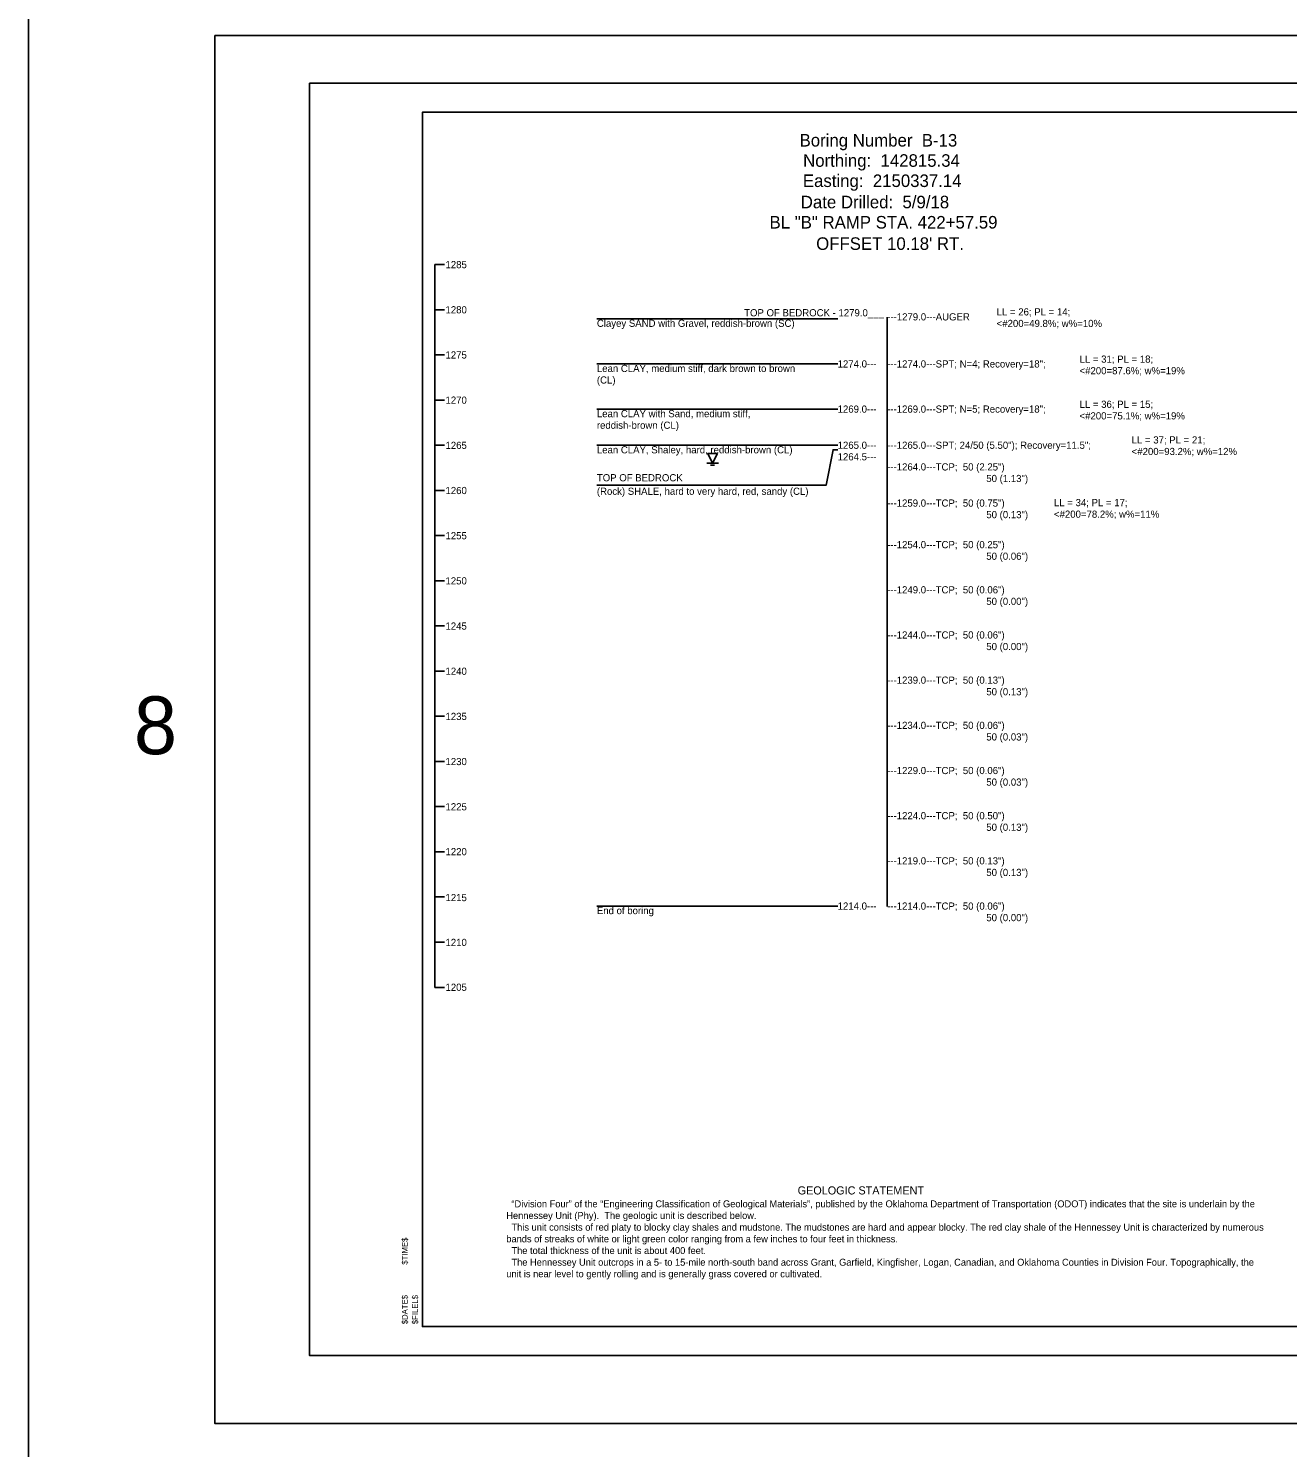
# Model space of a CAD drawing. Extents: x 2150162 to 2150245, y 143729 to 143865.
# Drawn here: x 2150203.4 to 2150225.17, y 143786.22 to 143810.76 of the extents above; entities that cross this region are included whole.
import ezdxf

# ---------------------------------------------------------------- set-up
doc = ezdxf.new("R2010")
doc.units = 0
for name, color, linetype in [('Default', 7, 'Continuous'), ('S', 7, 'Continuous'), ('SHT_Plot_Shape_Full', 7, 'Continuous'), ('SHT_Plot_Shape_Half', 7, 'Continuous'), ('SHT_Plot_Stamp', 7, 'Continuous'), ('SHT_Sheet_Border', 7, 'Continuous'), ('Text', 7, 'Continuous')]:
    doc.layers.add(name, color=color, linetype=linetype)

# ---------------------------------------------------------------- blocks, each defined once
blk = doc.blocks.new('Stamp_Plot_Stamp')
at = {"layer": 'SHT_Plot_Stamp'}
for s, p in [('$TIME$', (1.695, 1.572)), ('$DATE$', (1.695, 0.542)), ('$FILEL$', (1.873, 0.542))]:
    blk.add_text(s, height=0.1, rotation=90, dxfattribs=at).set_placement(p)
blk = doc.blocks.new('DGRFC_WTLEV1')
at = {"layer": 'Default'}
for points in [[(-0.0127, 0), (0.0127, 0)], [(0, 0), (0.0106, 0.0212), (-0.0106, 0.0212), (0, 0)], [(-0.0042, -0.0042), (0.0042, -0.0042)]]:
    blk.add_lwpolyline(points, dxfattribs=at)

msp = doc.modelspace()

# ---------------------------------------------------------------- linework, layer by layer
at = {"layer": 'Default'}
msp.add_line((2150210.432, 143794.179), (2150210.432, 143806.679), dxfattribs=at)
for points in [[(2150210.432, 143806.679), (2150210.599, 143806.679)], [(2150210.432, 143805.898), (2150210.599, 143805.898)], [(2150213.231, 143805.742), (2150217.398, 143805.742)], [(2150218.251, 143805.769), (2150218.251, 143795.579)], [(2150210.432, 143805.117), (2150210.599, 143805.117)], [(2150213.231, 143804.96), (2150217.398, 143804.96)], [(2150210.432, 143804.335), (2150210.599, 143804.335)], [(2150210.432, 143804.335), (2150210.599, 143804.335)], [(2150213.231, 143804.179), (2150217.398, 143804.179)], [(2150210.432, 143803.554), (2150210.599, 143803.554)], [(2150213.231, 143803.554), (2150217.398, 143803.554)], [(2150213.231, 143802.866), (2150217.196, 143802.866), (2150217.315, 143803.476), (2150217.398, 143803.476)], [(2150210.432, 143802.773), (2150210.599, 143802.773)], [(2150210.432, 143801.992), (2150210.599, 143801.992)], [(2150210.432, 143801.21), (2150210.599, 143801.21)], [(2150210.432, 143800.429), (2150210.599, 143800.429)], [(2150210.432, 143799.648), (2150210.599, 143799.648)], [(2150210.432, 143798.867), (2150210.599, 143798.867)], [(2150210.432, 143798.085), (2150210.599, 143798.085)], [(2150210.432, 143797.304), (2150210.599, 143797.304)], [(2150210.432, 143796.523), (2150210.599, 143796.523)], [(2150210.432, 143795.742), (2150210.599, 143795.742)], [(2150213.231, 143795.585), (2150217.398, 143795.585)], [(2150210.432, 143794.96), (2150210.599, 143794.96)], [(2150210.432, 143794.179), (2150210.599, 143794.179)]]:
    msp.add_lwpolyline(points, dxfattribs=at)
at = {"layer": 'S'}
msp.add_lwpolyline([(2150203.404, 143865.061), (2150245.24, 143865.061), (2150245.24, 143729.315), (2150203.404, 143729.315)], close=True, dxfattribs=at)
at = {"layer": 'SHT_Plot_Shape_Full'}
msp.add_lwpolyline([(2150206.628, 143810.637), (2150242.628, 143810.637), (2150242.628, 143786.637), (2150206.628, 143786.637)], close=True, dxfattribs=at)
at = {"layer": 'SHT_Plot_Shape_Half'}
msp.add_lwpolyline([(2150208.265, 143809.812), (2150242.265, 143809.812), (2150242.265, 143787.812), (2150208.265, 143787.812)], close=True, dxfattribs=at)
at = {"layer": 'SHT_Sheet_Border'}
msp.add_lwpolyline([(2150241.715, 143788.312), (2150210.215, 143788.312), (2150210.215, 143809.312), (2150241.715, 143809.312)], close=True, dxfattribs=at)

# ---------------------------------------------------------------- block references
at = {"layer": 'Default', "xscale": 7.873999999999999, "yscale": 7.873999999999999}
msp.add_blockref('DGRFC_WTLEV1', (2150215.231, 143803.242), dxfattribs=at)
at = {"layer": 'SHT_Plot_Stamp'}
msp.add_blockref('Stamp_Plot_Stamp', (2150208.265, 143787.812), dxfattribs=at)

# ---------------------------------------------------------------- texts
at = {"layer": 'Default'}
for s, height, p in [('Boring Number  B-13', 0.217, (2150216.735, 143808.719)), ('Northing:  142815.34', 0.217, (2150216.796, 143808.369)), ('Easting:  2150337.14', 0.217, (2150216.792, 143808.019)), ('Date Drilled:  5/9/18', 0.217, (2150216.756, 143807.651)), ('BL "B" RAMP STA. 422+57.59', 0.217, (2150216.216, 143807.301)), ("OFFSET 10.18' RT.", 0.217, (2150217.022, 143806.932)), ('1285', 0.124, (2150210.614, 143806.615)), ('1280', 0.124, (2150210.614, 143805.834)), ('TOP OF BEDROCK - 1279.0___', 0.124, (2150215.777, 143805.783)), ('---1279.0---AUGER', 0.124, (2150218.25, 143805.712)), ('LL = 26; PL = 14;', 0.124, (2150220.142, 143805.798)), ('Clayey SAND with Gravel, reddish-brown (SC)', 0.124, (2150213.231, 143805.601)), ('<#200=49.8%; w%=10%', 0.124, (2150220.142, 143805.598)), ('1275', 0.124, (2150210.614, 143805.053)), ('LL = 31; PL = 18;', 0.124, (2150221.575, 143804.981)), ('Lean CLAY, medium stiff, dark brown to brown', 0.124, (2150213.231, 143804.82)), ('1274.0---', 0.124, (2150217.393, 143804.898)), ('---1274.0---SPT; N=4; Recovery=18";', 0.124, (2150218.249, 143804.898)), ('<#200=87.6%; w%=19%', 0.124, (2150221.575, 143804.781)), ('(CL)', 0.124, (2150213.231, 143804.62)), ('1270', 0.124, (2150210.614, 143804.272)), ('Lean CLAY with Sand, medium stiff,', 0.124, (2150213.231, 143804.038)), ('1269.0---', 0.124, (2150217.393, 143804.117)), ('---1269.0---SPT; N=5; Recovery=18";', 0.124, (2150218.249, 143804.117)), ('<#200=75.1%; w%=19%', 0.124, (2150221.575, 143804)), ('LL = 36; PL = 15;', 0.124, (2150221.575, 143804.2)), ('reddish-brown (CL)', 0.124, (2150213.231, 143803.838)), ('1265', 0.124, (2150210.614, 143803.49)), ('1265.0---', 0.124, (2150217.393, 143803.492)), ('---1265.0---SPT; 24/50 (5.50"); Recovery=11.5";', 0.124, (2150218.249, 143803.492)), ('LL = 37; PL = 21;', 0.124, (2150222.476, 143803.584)), ('Lean CLAY, Shaley, hard, reddish-brown (CL)', 0.124, (2150213.231, 143803.413)), ('1264.5---', 0.124, (2150217.393, 143803.292)), ('<#200=93.2%; w%=12%', 0.124, (2150222.476, 143803.384)), ('---1264.0---TCP;  50 (2.25")', 0.124, (2150218.249, 143803.117)), ('TOP OF BEDROCK', 0.124, (2150213.231, 143802.93)), ('50 (1.13")', 0.124, (2150219.963, 143802.917)), ('1260', 0.124, (2150210.614, 143802.709)), ('(Rock) SHALE, hard to very hard, red, sandy (CL)', 0.124, (2150213.231, 143802.696)), ('---1259.0---TCP;  50 (0.75")', 0.124, (2150218.249, 143802.492)), ('LL = 34; PL = 17;', 0.124, (2150221.133, 143802.5)), ('50 (0.13")', 0.124, (2150219.963, 143802.292)), ('<#200=78.2%; w%=11%', 0.124, (2150221.133, 143802.3)), ('1255', 0.124, (2150210.614, 143801.928)), ('---1254.0---TCP;  50 (0.25")', 0.124, (2150218.249, 143801.773)), ('50 (0.06")', 0.124, (2150219.963, 143801.573)), ('1250', 0.124, (2150210.614, 143801.147)), ('---1249.0---TCP;  50 (0.06")', 0.124, (2150218.249, 143800.992)), ('50 (0.00")', 0.124, (2150219.963, 143800.792)), ('1245', 0.124, (2150210.614, 143800.365)), ('---1244.0---TCP;  50 (0.06")', 0.124, (2150218.249, 143800.211)), ('50 (0.00")', 0.124, (2150219.963, 143800.011)), ('1240', 0.124, (2150210.614, 143799.584)), ('---1239.0---TCP;  50 (0.13")', 0.124, (2150218.249, 143799.43)), ('50 (0.13")', 0.124, (2150219.963, 143799.23)), ('1235', 0.124, (2150210.614, 143798.803)), ('---1234.0---TCP;  50 (0.06")', 0.124, (2150218.249, 143798.648)), ('50 (0.03")', 0.124, (2150219.963, 143798.448)), ('1230', 0.124, (2150210.614, 143798.022)), ('---1229.0---TCP;  50 (0.06")', 0.124, (2150218.249, 143797.867)), ('50 (0.03")', 0.124, (2150219.963, 143797.667)), ('1225', 0.124, (2150210.614, 143797.24)), ('---1224.0---TCP;  50 (0.50")', 0.124, (2150218.249, 143797.086)), ('50 (0.13")', 0.124, (2150219.963, 143796.886)), ('1220', 0.124, (2150210.614, 143796.464)), ('---1219.0---TCP;  50 (0.13")', 0.124, (2150218.249, 143796.305)), ('50 (0.13")', 0.124, (2150219.963, 143796.105)), ('1215', 0.124, (2150210.614, 143795.67)), ('End of boring', 0.124, (2150213.231, 143795.445)), ('1214.0---', 0.124, (2150217.393, 143795.523)), ('---1214.0---TCP;  50 (0.06")', 0.124, (2150218.249, 143795.523)), ('50 (0.00")', 0.124, (2150219.963, 143795.323)), ('1210', 0.124, (2150210.614, 143794.895)), ('1205', 0.124, (2150210.614, 143794.119))]:
    msp.add_text(s, height=height, dxfattribs=at).set_placement(p)
at = {"layer": 'S'}
msp.add_text('8', height=1, dxfattribs=at).set_placement((2150205.229, 143798.211))
at = {"layer": 'Text'}
for s, height, p in [('GEOLOGIC STATEMENT', 0.14, (2150216.702, 143790.598)), ('  “Division Four” of the “Engineering Classification of Geological Materials”, published by the Oklahoma Department of Transportation (ODOT) indicates that the site is underlain by the ', 0.12, (2150211.665, 143790.376)), ('Hennessey Unit (Phy).  The geologic unit is described below. ', 0.12, (2150211.665, 143790.174)), ('bands of streaks of white or light green color ranging from a few inches to four feet in thickness. ', 0.12, (2150211.665, 143789.77)), ('  This unit consists of red platy to blocky clay shales and mudstone. The mudstones are hard and appear blocky. The red clay shale of the Hennessey Unit is characterized by numerous ', 0.12, (2150211.665, 143789.972)), ('  The total thickness of the unit is about 400 feet.', 0.12, (2150211.665, 143789.568)), ('  The Hennessey Unit outcrops in a 5- to 15-mile north-south band across Grant, Garfield, Kingfisher, Logan, Canadian, and Oklahoma Counties in Division Four. Topographically, the ', 0.12, (2150211.665, 143789.366)), ('unit is near level to gently rolling and is generally grass covered or cultivated.', 0.12, (2150211.665, 143789.166))]:
    msp.add_text(s, height=height, dxfattribs=at).set_placement(p)

doc.saveas('drawing.dxf')
